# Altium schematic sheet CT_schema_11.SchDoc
size 274 x 160 mm
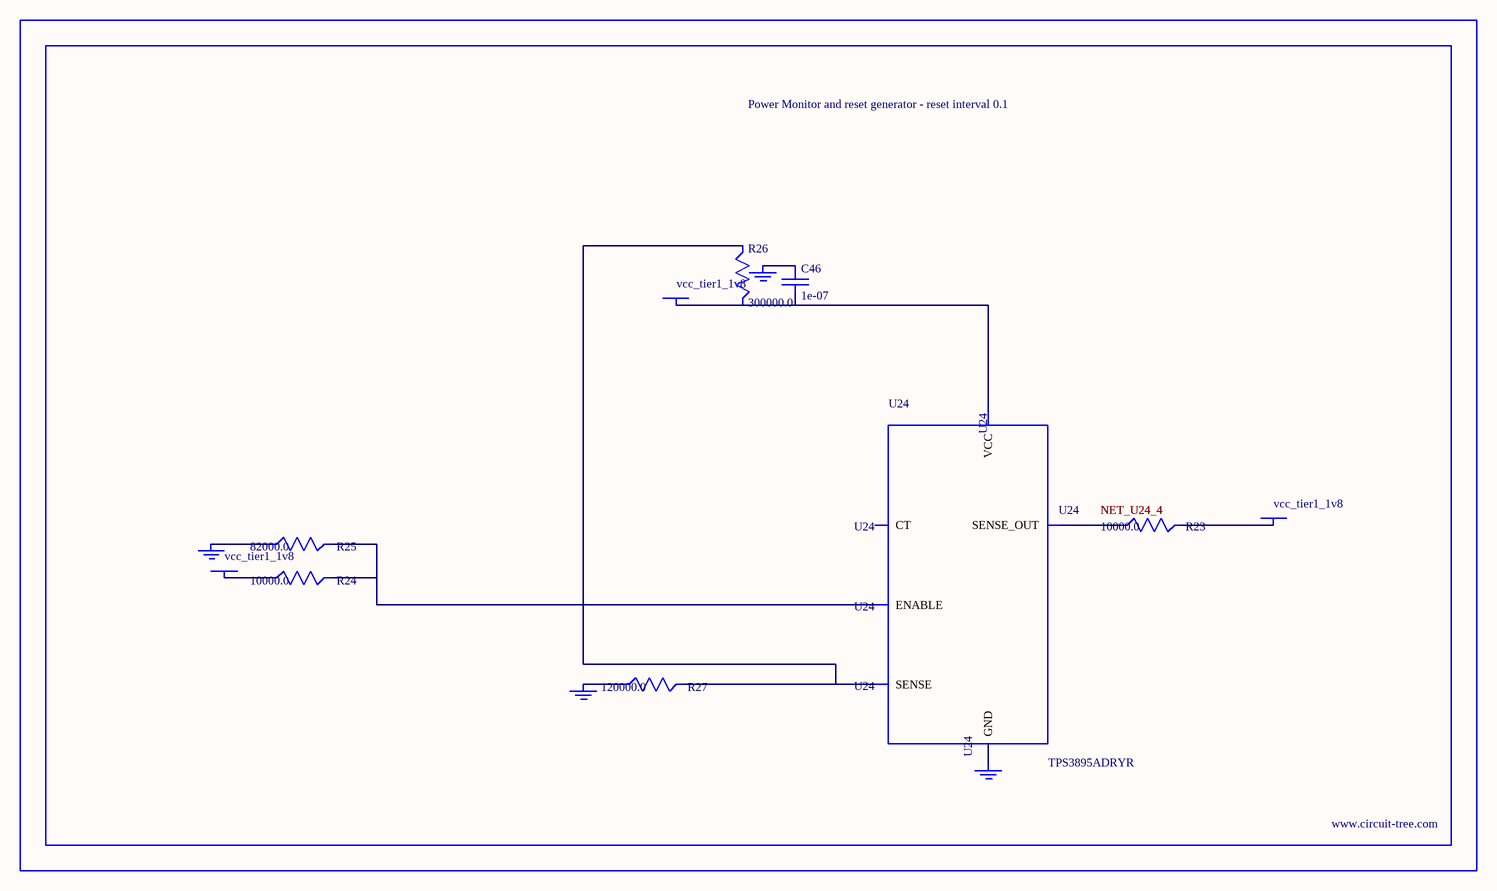
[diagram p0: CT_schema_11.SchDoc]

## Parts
BORDER10  (no value)
C46  1e-07  [C0402]
GND_INSTANCE_10_0  (no value)
GND_INSTANCE_10_1  (no value)
GND_INSTANCE_10_2  (no value)
GND_INSTANCE_10_3  (no value)
POWER_INSTANCE_10_0  vcc_tier1_1v8
POWER_INSTANCE_10_1  vcc_tier1_1v8
POWER_INSTANCE_10_2  vcc_tier1_1v8
R23  10000.0  [R0603]
R24  10000.0  [R0603]
R25  82000.0  [R0603]
R26  300000.0  [R0603]
R27  120000.0  [R0603]
U24  TPS3895ADRYR  [SON-6]

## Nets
NetC46_1: C46.1 GND_INSTANCE_10_2.0(GND)
NetC46_2: C46.2 POWER_INSTANCE_10_2.0(PWR) R26.2 U24.6(VCC)
NetGND_INSTANCE_10_0_0: GND_INSTANCE_10_0.0(GND) R25.1
NetGND_INSTANCE_10_1_0: GND_INSTANCE_10_1.0(GND) R27.1
NetGND_INSTANCE_10_3_0: GND_INSTANCE_10_3.0(GND) U24.2(GND)
NetPOWER_INSTANCE_10_0_0: POWER_INSTANCE_10_0.0(PWR) R24.1
NetPOWER_INSTANCE_10_1_0: POWER_INSTANCE_10_1.0(PWR) R23.2
NetR23_1: R23.1 U24.4(SENSE_OUT)
NetR24_2: R24.2 R25.2 U24.1(ENABLE)
NetR26_1: R26.1 R27.2 U24.3(SENSE)

Not connected (* = marked no-connect by the designer): U24 5(CT)

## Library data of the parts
BORDER10 = BORDER_PAGE10
C46 = C0402C104K3RACTU
GND_INSTANCE_10_0-GND_INSTANCE_10_3 = GND
POWER_INSTANCE_10_0-POWER_INSTANCE_10_2 = PWR
R23 R24 = RC0603JR-0710KL
R25 = RC0603JR-0782KL
R26 = RC0603JR-07300KL
R27 = RC0603JR-07120KL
